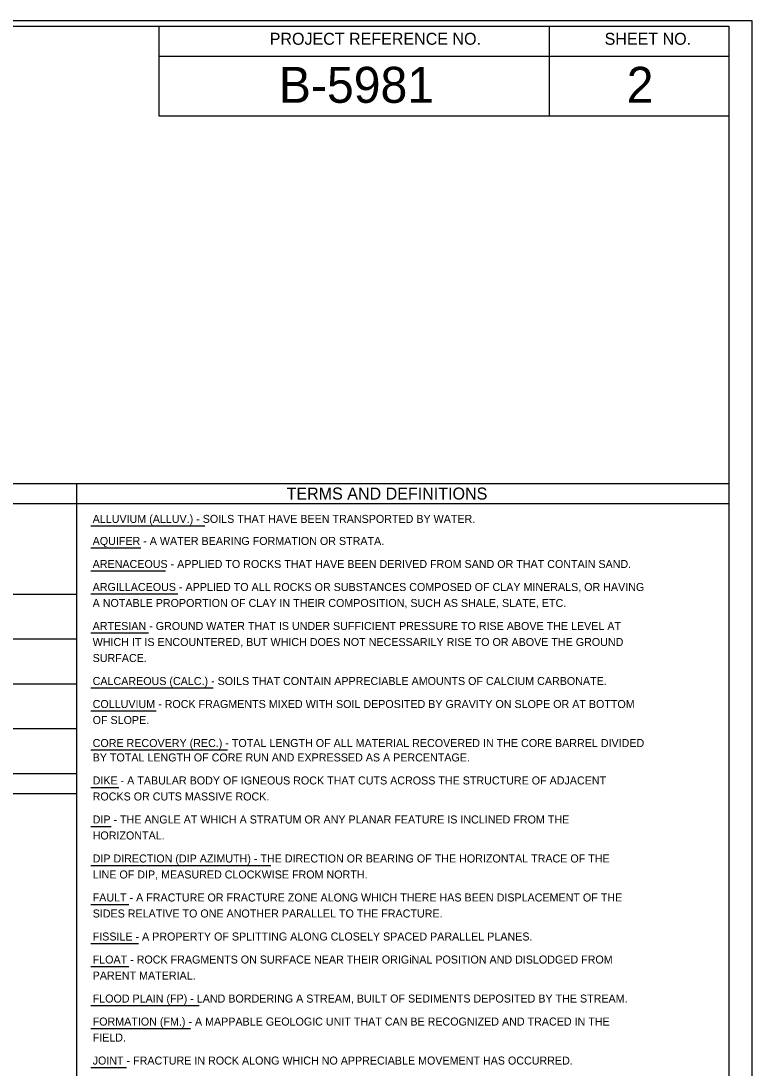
# Model space of a CAD drawing. Extents: x 265553 to 275568, y 168312 to 173522.
# Drawn here: x 268037 to 268433, y 170735 to 171303 of the extents above; entities that cross this region are included whole.
import ezdxf

# ---------------------------------------------------------------- set-up
doc = ezdxf.new("R2010")
doc.units = 0
for name, color, linetype in [('Geotech Sheets and Borders Cell', 7, 'Continuous'), ('Scratch_Level_0', 7, 'Continuous'), ('Sheet Plot Border Inside CELL', 7, 'Continuous')]:
    doc.layers.add(name, color=color, linetype=linetype)

msp = doc.modelspace()

# ---------------------------------------------------------------- linework, layer by layer
at = {"layer": 'Geotech Sheets and Borders Cell'}
for p, q in [((268322.94, 171299.94), (268322.94, 171251.19)), ((268111.67, 171283.69), (268420.42, 171283.69)), ((266920.42, 171052.08), (268420.42, 171052.08)), ((268066.96, 171052.08), (268066.96, 170249.94)), ((266920.42, 171041.24), (268420.42, 171041.24)), ((268074.77, 171029.18), (268136.43, 171029.18)), ((268074.77, 171017.22), (268101.85, 171017.22)), ((268074.77, 171004.75), (268115.15, 171004.75)), ((268066.96, 170992), (267670.42, 170992)), ((268074.77, 170992.28), (268121.76, 170992.28)), ((268066.96, 170967.71), (267670.42, 170967.71)), ((268074.77, 170971.14), (268105.9, 170971.14)), ((268066.96, 170943.42), (267670.42, 170943.42)), ((268074.77, 170941.33), (268140.99, 170941.33)), ((268074.77, 170928.86), (268110.17, 170928.86)), ((268066.96, 170919.12), (267670.42, 170919.12)), ((268074.77, 170907.72), (268148.83, 170907.72)), ((268066.96, 170894.83), (267670.42, 170894.83)), ((268074.77, 170887.44), (268089.91, 170887.44)), ((268066.96, 170883.98), (267670.42, 170883.98)), ((268074.77, 170866.3), (268085.77, 170866.3)), ((268074.77, 170845.16), (268172.2, 170845.16)), ((268074.77, 170824.02), (268095.27, 170824.02)), ((268074.77, 170802.88), (268100.51, 170802.88)), ((268074.77, 170790.4), (268095.27, 170790.4)), ((268074.77, 170769.26), (268133.42, 170769.26)), ((268074.77, 170756.79), (268128.79, 170756.79)), ((268074.77, 170735.65), (268094.05, 170735.65))]:
    msp.add_line(p, q, dxfattribs=at)
for points in [[(266920.42, 171299.94), (268420.42, 171299.94), (268420.42, 170249.94), (266920.42, 170249.94)], [(268111.67, 171299.94), (268420.42, 171299.94), (268420.42, 171251.19), (268111.67, 171251.19)]]:
    msp.add_lwpolyline(points, close=True, dxfattribs=at)
at = {"layer": 'Scratch_Level_0'}
msp.add_line((268432.92, 171302.77), (268432.92, 171302.77), dxfattribs=at)
at = {"layer": 'Sheet Plot Border Inside CELL'}
msp.add_lwpolyline([(266765.25, 170247.11), (268432.92, 170247.11), (268432.92, 171302.77), (266765.25, 171302.77)], close=True, dxfattribs=at)

# ---------------------------------------------------------------- texts
at = {"layer": 'Geotech Sheets and Borders Cell'}
for s, height, p in [('PROJECT REFERENCE NO.', 6.4997, (268171.63, 171289.85)), ('SHEET NO.', 6.5, (268353.05, 171289.85)), ('B-5981', 19.5, (268176.57, 171258.4)), ('2', 19.5, (268365.03, 171258.4)), ('TERMS AND DEFINITIONS', 6.507, (268180.75, 171043.41)), ('ALLUVIUM (ALLUV.) - SOILS THAT HAVE BEEN TRANSPORTED BY WATER.', 4.3381, (268075.71, 171030.76)), ('AQUIFER - A WATER BEARING FORMATION OR STRATA.', 4.3381, (268075.71, 171018.81)), ('ARENACEOUS - APPLIED TO ROCKS THAT HAVE BEEN DERIVED FROM SAND OR THAT CONTAIN SAND.', 4.3381, (268075.71, 171006.33)), ('ARGILLACEOUS - APPLIED TO ALL ROCKS OR SUBSTANCES COMPOSED OF CLAY MINERALS, OR HAVING', 4.3381, (268075.71, 170993.86)), ('A NOTABLE PROPORTION OF CLAY IN THEIR COMPOSITION, SUCH AS SHALE, SLATE, ETC.', 4.3381, (268075.71, 170985.19)), ('ARTESIAN - GROUND WATER THAT IS UNDER SUFFICIENT PRESSURE TO RISE ABOVE THE LEVEL AT', 4.3381, (268075.71, 170972.72)), ('WHICH IT IS ENCOUNTERED, BUT WHICH DOES NOT NECESSARILY RISE TO OR ABOVE THE GROUND', 4.3381, (268075.71, 170964.05)), ('SURFACE.', 4.338, (268075.71, 170955.38)), ('CALCAREOUS (CALC.) - SOILS THAT CONTAIN APPRECIABLE AMOUNTS OF CALCIUM CARBONATE.', 4.3381, (268075.71, 170942.91)), ('COLLUVIUM - ROCK FRAGMENTS MIXED WITH SOIL DEPOSITED BY GRAVITY ON SLOPE OR AT BOTTOM ', 4.3381, (268075.71, 170930.44)), ('OF SLOPE.', 4.338, (268075.71, 170921.77)), ('CORE RECOVERY (REC.) - TOTAL LENGTH OF ALL MATERIAL RECOVERED IN THE CORE BARREL DIVIDED', 4.3381, (268075.71, 170909.3)), ('BY TOTAL LENGTH OF CORE RUN AND EXPRESSED AS A PERCENTAGE.', 4.3381, (268075.71, 170901.49)), ('DIKE - A TABULAR BODY OF IGNEOUS ROCK THAT CUTS ACROSS THE STRUCTURE OF ADJACENT', 4.3381, (268075.71, 170889.02)), ('ROCKS OR CUTS MASSIVE ROCK.', 4.3381, (268075.71, 170880.35)), ('DIP - THE ANGLE AT WHICH A STRATUM OR ANY PLANAR FEATURE IS INCLINED FROM THE', 4.3381, (268075.71, 170867.88)), ('HORIZONTAL.', 4.3381, (268075.71, 170859.21)), ('DIP DIRECTION (DIP AZIMUTH) - THE DIRECTION OR BEARING OF THE HORIZONTAL TRACE OF THE', 4.3381, (268075.71, 170846.74)), ('LINE OF DIP, MEASURED CLOCKWISE FROM NORTH.', 4.3381, (268075.71, 170838.07)), ('FAULT - A FRACTURE OR FRACTURE ZONE ALONG WHICH THERE HAS BEEN DISPLACEMENT OF THE', 4.3381, (268075.71, 170825.6)), ('SIDES RELATIVE TO ONE ANOTHER PARALLEL TO THE FRACTURE.', 4.3381, (268075.71, 170816.93)), ('FISSILE - A PROPERTY OF SPLITTING ALONG CLOSELY SPACED PARALLEL PLANES.', 4.3381, (268075.71, 170804.46)), ('FLOAT - ROCK FRAGMENTS ON SURFACE NEAR THEIR ORIGiNAL POSITION AND DISLODGED FROM', 4.3381, (268075.71, 170791.98)), ('PARENT MATERIAL.', 4.3381, (268075.71, 170783.32)), ('FLOOD PLAIN (FP) - LAND BORDERING A STREAM, BUILT OF SEDIMENTS DEPOSITED BY THE STREAM.', 4.3381, (268075.71, 170770.84)), ('FORMATION (FM.) - A MAPPABLE GEOLOGIC UNIT THAT CAN BE RECOGNIZED AND TRACED IN THE', 4.3381, (268075.71, 170758.37)), ('FIELD.', 4.338, (268075.71, 170749.7)), ('JOINT - FRACTURE IN ROCK ALONG WHICH NO APPRECIABLE MOVEMENT HAS OCCURRED.', 4.3381, (268075.71, 170737.23))]:
    msp.add_text(s, height=height, dxfattribs=at).set_placement(p)

doc.saveas('drawing.dxf')
